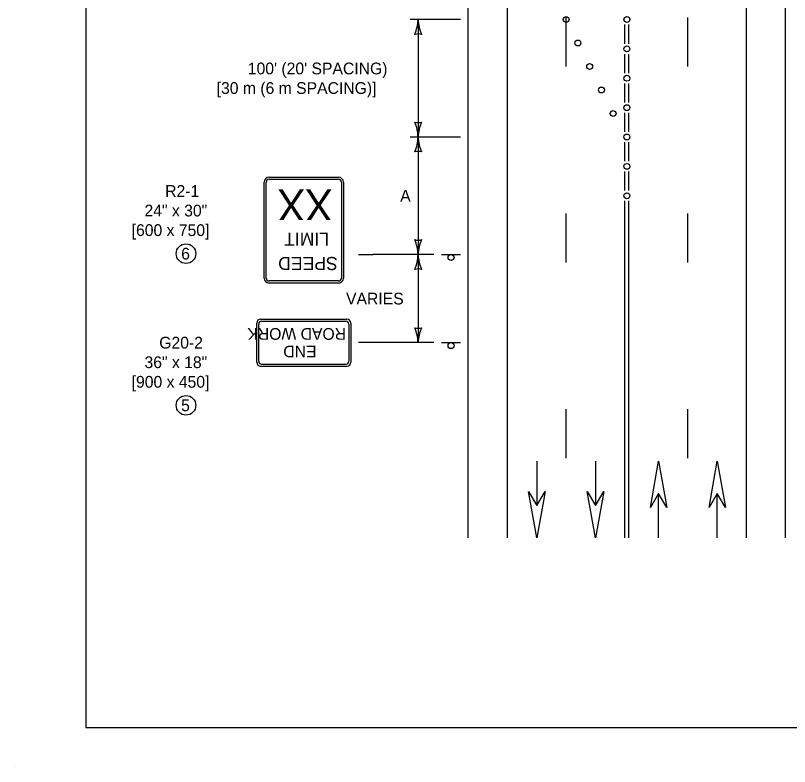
# Model space of a CAD drawing. Extents: x 49991.4 to 50021, y 49987.6 to 50011.4.
# Drawn here: x 49999.977 to 50003.928, y 49999.862 to 50003.697 of the extents above; entities that cross this region are included whole.
import ezdxf

# ---------------------------------------------------------------- set-up
doc = ezdxf.new("R2010")
doc.units = 0
for name, color, linetype in [('Level 1', 7, 'Continuous'), ('Level 2', 7, 'Continuous'), ('Level 3', 7, 'Continuous')]:
    doc.layers.add(name, color=color, linetype=linetype)

msp = doc.modelspace()

# ---------------------------------------------------------------- linework, layer by layer
at = {"layer": 'Level 1'}
for p, q in [((50002.2878, 50001.0309), (50002.2878, 50009.6868)), ((50002.4877, 50001.0309), (50002.4877, 50009.6868)), ((50003.7077, 50001.0309), (50003.7077, 50009.6868)), ((50003.9076, 50001.0309), (50003.9076, 50009.6868)), ((50002.7879, 50003.4368), (50002.7879, 50003.6868)), ((50003.0877, 50003.5529), (50003.0877, 50003.6505)), ((50003.1077, 50003.5529), (50003.1077, 50003.6505)), ((50003.4079, 50003.4368), (50003.4079, 50003.6868)), ((50003.0877, 50003.4029), (50003.0877, 50003.5005)), ((50003.1077, 50003.4029), (50003.1077, 50003.5005)), ((50003.0877, 50003.2529), (50003.0877, 50003.3505)), ((50003.1077, 50003.2529), (50003.1077, 50003.3505)), ((50003.0877, 50003.1029), (50003.0877, 50003.2005)), ((50003.1077, 50003.1029), (50003.1077, 50003.2005)), ((50003.0877, 50002.9529), (50003.0877, 50003.0505)), ((50003.1077, 50002.9529), (50003.1077, 50003.0505)), ((50003.0877, 50002.8029), (50003.0877, 50002.9005)), ((50003.1077, 50002.8029), (50003.1077, 50002.9005)), ((50001.2709, 50002.8712), (50001.6253, 50002.8712)), ((50001.2709, 50002.8607), (50001.6253, 50002.8607)), ((50001.2455, 50002.3564), (50001.2455, 50002.8459)), ((50001.2561, 50002.3564), (50001.2561, 50002.8459)), ((50001.6401, 50002.8459), (50001.6401, 50002.3564)), ((50001.6506, 50002.8459), (50001.6506, 50002.3564)), ((50003.0877, 50001.0309), (50003.0877, 50002.7505)), ((50003.1077, 50001.0309), (50003.1077, 50002.7505)), ((50002.7879, 50002.4368), (50002.7879, 50002.6868)), ((50003.4079, 50002.4368), (50003.4079, 50002.6868)), ((50002.1518, 50002.4767), (50002.2478, 50002.4767)), ((50001.6253, 50002.3417), (50001.2709, 50002.3417)), ((50001.6253, 50002.3311), (50001.2709, 50002.3311)), ((50001.4481, 50002.3311), (50001.4481, 50002.3311)), ((50001.208, 50001.9267), (50001.208, 50002.1267)), ((50001.218, 50001.9317), (50001.218, 50002.1217)), ((50001.2281, 50002.1467), (50001.6681, 50002.1467)), ((50001.233, 50002.1367), (50001.663, 50002.1367)), ((50001.678, 50002.1217), (50001.678, 50001.9317)), ((50001.688, 50002.1267), (50001.688, 50001.9267)), ((50002.1518, 50002.0267), (50002.2478, 50002.0267)), ((50001.233, 50001.9167), (50001.663, 50001.9167)), ((50001.228, 50001.9067), (50001.668, 50001.9067)), ((50002.7879, 50001.4368), (50002.7879, 50001.6868)), ((50002.7879, 50001.4368), (50002.7879, 50001.6868)), ((50002.7879, 50001.4368), (50002.7879, 50001.6868)), ((50003.4079, 50001.4368), (50003.4079, 50001.6868)), ((50003.4079, 50001.4368), (50003.4079, 50001.6868)), ((50003.4079, 50001.4368), (50003.4079, 50001.6868)), ((50002.6377, 50001.421), (50002.6377, 50001.1951)), ((50002.6381, 50001.421), (50002.6381, 50001.1951)), ((50002.9371, 50001.421), (50002.9371, 50001.1951)), ((50002.9375, 50001.421), (50002.9375, 50001.1951)), ((50003.2594, 50001.0309), (50003.2594, 50001.2568)), ((50003.2596, 50001.0309), (50003.2596, 50001.2568)), ((50003.5588, 50001.0308), (50003.5588, 50001.2567)), ((50003.559, 50001.0308), (50003.559, 50001.2567)), ((49999.9766, 49999.8624), (49999.9766, 49999.8624))]:
    msp.add_line(p, q, dxfattribs=at)
for points in [[(50008.6146, 50011.2628), (50000.3356, 50011.2628), (50000.3356, 50000.0624), (50008.6146, 50000.0624)], [(50003.2176, 50001.1845), (50003.2594, 50001.421), (50003.3012, 50001.1845), (50003.2594, 50001.2567)], [(50003.517, 50001.1844), (50003.5588, 50001.4209), (50003.6006, 50001.1844), (50003.5588, 50001.2566)], [(50002.6797, 50001.2674), (50002.6381, 50001.0309), (50002.5961, 50001.2674), (50002.6381, 50001.1952)], [(50002.9791, 50001.2674), (50002.9375, 50001.0309), (50002.8955, 50001.2674), (50002.9375, 50001.1952)]]:
    msp.add_lwpolyline(points, close=True, dxfattribs=at)
for centre, radius in [((50002.7876, 50003.6767), 0.015), ((50003.0977, 50003.6767), 0.015), ((50002.8476, 50003.5567), 0.015), ((50003.0977, 50003.5267), 0.015), ((50002.9075, 50003.4367), 0.015), ((50003.0977, 50003.3767), 0.015), ((50002.9675, 50003.3167), 0.015), ((50003.0977, 50003.2267), 0.015), ((50003.0275, 50003.1967), 0.015), ((50003.0977, 50003.0767), 0.015), ((50003.0977, 50002.9267), 0.015), ((50003.0977, 50002.7767), 0.015), ((50002.1999, 50002.4615), 0.0152), ((50002.1999, 50002.0115), 0.0152)]:
    msp.add_circle(centre, radius, dxfattribs=at)
for centre, radius, start, end in [((50001.2709, 50002.8459), 0.0253, 90, 180), ((50001.2709, 50002.8459), 0.0148, 90, 180), ((50001.6253, 50002.8459), 0.0253, 360, 90), ((50001.6253, 50002.8459), 0.0148, 360, 90), ((50001.2709, 50002.3564), 0.0253, 180, 270), ((50001.2709, 50002.3564), 0.0148, 180, 270), ((50001.6253, 50002.3564), 0.0148, 270, 360), ((50001.6253, 50002.3564), 0.0253, 270, 360), ((50001.2281, 50002.1267), 0.02, 90, 180), ((50001.233, 50002.1217), 0.015, 90, 180), ((50001.663, 50002.1217), 0.015, 360, 90), ((50001.6681, 50002.1267), 0.02, 360, 90), ((50001.228, 50001.9267), 0.02, 180, 270), ((50001.233, 50001.9317), 0.015, 180, 270), ((50001.663, 50001.9317), 0.015, 270, 360), ((50001.668, 50001.9267), 0.02, 270, 360)]:
    msp.add_arc(centre, radius, start, end, dxfattribs=at)
at = {"layer": 'Level 2'}
for centre in [(50000.847, 50002.4811), (50000.847, 50001.7067)]:
    msp.add_circle(centre, 0.0501, dxfattribs=at)
at = {"layer": 'Level 3'}
for p, q in [((50002.2478, 50003.6767), (50001.9918, 50003.6767)), ((50002.0318, 50003.6767), (50002.0318, 50003.0767)), ((50002.2478, 50003.0767), (50001.9918, 50003.0767)), ((50002.0318, 50003.0767), (50002.0318, 50002.4767)), ((50001.728, 50002.4767), (50001.8025, 50002.4767)), ((50002.1118, 50002.4767), (50001.8025, 50002.4767)), ((50002.0318, 50002.4767), (50002.0318, 50002.0267)), ((50002.1118, 50002.0267), (50001.728, 50002.0267))]:
    msp.add_line(p, q, dxfattribs=at)
for centre, radius, start, end in [((50001.7991, 50003.6882), 0.233, 337.9228, 357.1727), ((50002.254, 50003.6859), 0.2223, 182.3605, 202.544), ((50002.0318, 50003.5485), 0.0548, 72.1388, 107.8612), ((50001.8097, 50003.0675), 0.2223, 2.3605, 22.544), ((50002.0318, 50003.2049), 0.0548, 252.1388, 287.8612), ((50002.2645, 50003.0652), 0.233, 157.9228, 177.1727), ((50001.8097, 50003.0859), 0.2223, 337.456, 357.6395), ((50002.2645, 50003.0882), 0.233, 182.8273, 202.0772), ((50002.0318, 50002.9485), 0.0548, 72.1388, 107.8612), ((50002.0318, 50002.6049), 0.0548, 252.1388, 287.8612), ((50001.7991, 50002.4652), 0.233, 2.8273, 22.0772), ((50002.254, 50002.4675), 0.2223, 157.456, 177.6395), ((50001.8097, 50002.4859), 0.2223, 337.456, 357.6395), ((50002.2645, 50002.4882), 0.233, 182.8273, 202.0772), ((50002.0318, 50002.3485), 0.0548, 72.1388, 107.8612), ((50002.0318, 50002.1549), 0.0548, 252.1388, 287.8612), ((50001.7991, 50002.0152), 0.233, 2.8273, 22.0772), ((50002.254, 50002.0175), 0.2223, 157.456, 177.6395)]:
    msp.add_arc(centre, radius, start, end, dxfattribs=at)

# ---------------------------------------------------------------- texts
at = {"layer": 'Level 1'}
for s, height, p in [('XX', 0.15773, (50001.5952, 50002.8101)), ('LIMIT', 0.06695, (50001.5769, 50002.5882)), ('SPEED', 0.06695, (50001.6212, 50002.4644)), ('ROAD WORK', 0.06, (50001.6638, 50002.1013)), ('END', 0.06, (50001.5132, 50002.0113))]:
    msp.add_text(s, height=height, rotation=180, dxfattribs=at).set_placement(p)
at = {"layer": 'Level 2'}
for s, height, p in [("100' (20' SPACING)", 0.06, (50001.1625, 50003.3967)), ('[30 m (6 m SPACING)]', 0.06, (50001.0035, 50003.2967)), ('R2-1', 0.06, (50000.7407, 50002.7712)), ('24" x 30"', 0.06, (50000.6352, 50002.6712)), ('[600 x 750]', 0.06, (50000.5696, 50002.5712)), ('6', 0.06, (50000.8225, 50002.4511)), ('G20-2', 0.06, (50000.7104, 50001.9967)), ('36" x 18"', 0.06, (50000.6352, 50001.8967)), ('[900 x 450]', 0.06, (50000.5696, 50001.7967)), ('5', 0.0601, (50000.822, 50001.6767))]:
    msp.add_text(s, height=height, dxfattribs=at).set_placement(p)
for s, p in [('A', (50001.9403, 50002.7467)), ('VARIES', (50001.6639, 50002.2217))]:
    msp.add_text(s, height=0.06, rotation=360, dxfattribs=at).set_placement(p)

doc.saveas('drawing.dxf')
